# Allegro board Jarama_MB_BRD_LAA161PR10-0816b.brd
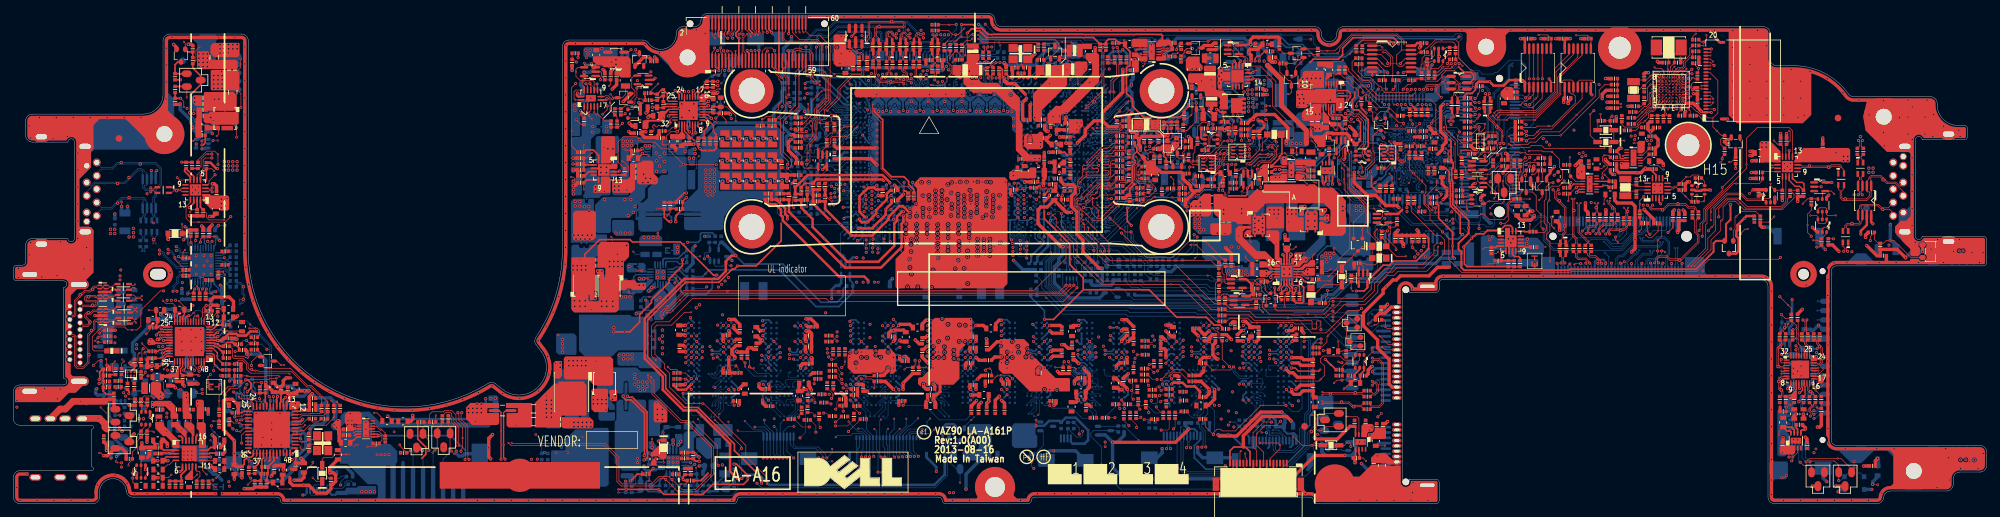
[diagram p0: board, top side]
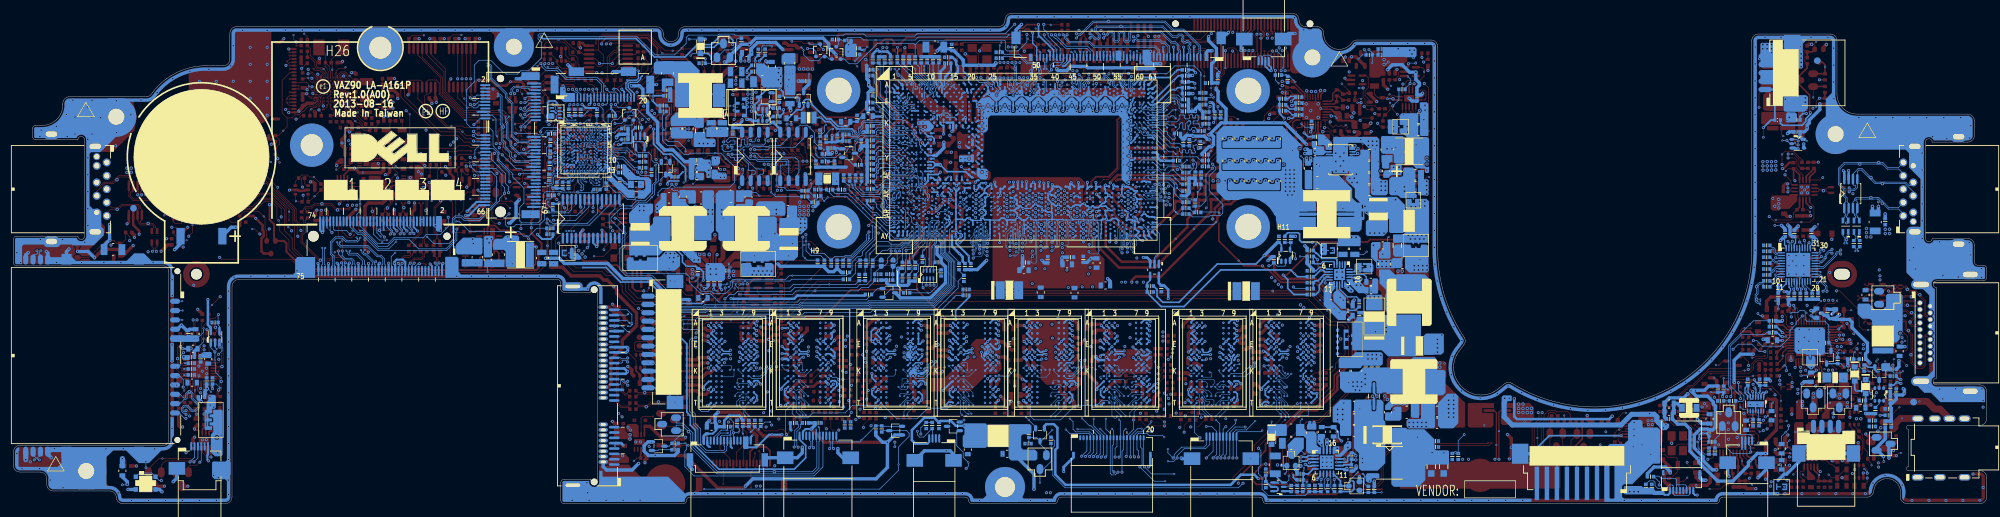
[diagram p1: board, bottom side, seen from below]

Outline 295.3 x 73.5 mm; copper layers: TOP, GND1, IN1, VCC, IN2, IN3, GND2, IN4, GND3, BOTTOM. Coordinates in mm from the lower left corner of the outline.
Outline path: 0,35.25 arc(0.15,35.6) 0.5,35.75 1.34,35.75 arc(1.69,35.9) 1.84,36.25 1.84,38.75 arc(2.13,39.46) 2.84,39.75 8.15,39.75 arc(8.65,39.25) 9.15,39.75 9.15,54.2 arc(8.65,54.7) 8.15,54.2 2.84,54.2 arc(2.13,54.49) 1.84,55.2 1.84,57.4 arc(2.13,58.11) 2.84,58.4 19.4,58.4 arc(21.52,59.28) 22.4,61.4 22.4,69.4 arc(22.69,70.11) 23.4,70.4 34.15,70.4 arc(34.86,70.11) 35.15,69.4 35.15,38 arc(47.22,17.47) 71.03,18.02 arc(71.62,18.17) 72.18,17.95 73.13,17.18 arc(76.07,16.31) 78.76,17.77 78.88,17.92 arc(79.77,20.36) 78.97,22.84 78.24,23.81 arc(78.04,24.38) 78.2,24.97 arc(81.14,31.19) 82.15,38 82.15,68.5 arc(82.44,69.21) 83.15,69.5 94.2,69.5 arc(94.66,69.39) 95.02,69.08 arc(97.59,68.21) 99.2,70.4 99.2,70.5 arc(99.49,71.21) 100.2,71.5 101.9,71.5 arc(102.61,71.79) 102.9,72.5 arc(103.19,73.21) 103.9,73.5 145.9,73.5 arc(146.61,73.21) 146.9,72.5 arc(147.19,71.79) 147.9,71.5 194.75,71.5 arc(195.46,71.21) 195.75,70.5 195.75,70.4 arc(196.9,69.25) 198.05,70.4 198.05,70.5 arc(198.34,71.21) 199.05,71.5 261.9,71.5 arc(262.61,71.21) 262.9,70.5 262.9,66.65 arc(263.19,65.94) 263.9,65.65 266.45,65.65 arc(271.05,64.53) 274.62,61.42 arc(274.97,61.11) 275.43,61 286.9,61 arc(287.61,60.71) 287.9,60 287.9,59.8 arc(288.81,57.61) 291,56.7 291.95,56.7 arc(292.3,56.55) 292.45,56.2 292.45,55.05 arc(292.3,54.7) 291.95,54.55 285.65,54.55 arc(285.15,55.05) 284.65,54.55 284.65,40.1 arc(285.15,39.6) 285.65,40.1 294.8,40.1 arc(295.15,39.95) 295.3,39.6 295.3,36.14 arc(295.15,35.79) 294.8,35.64 272.85,35.64 arc(272.28,35.41) 272.05,34.84 272.05,9.54 arc(272.28,8.97) 272.85,8.74 294.3,8.74 arc(295.01,8.45) 295.3,7.74 295.3,5.74 arc(295.01,5.03) 294.3,4.74 291.3,4.74 arc(290.59,4.45) 290.3,3.74 290.3,2.9 arc(290.01,2.19) 289.3,1.9 280.9,1.9 arc(280.21,1.62) 279.9,0.95 arc(279.59,0.28) 278.9,0 263.58,0 arc(262.87,0.29) 262.58,1 262.58,32.59 arc(262.29,33.3) 261.58,33.59 213.88,33.59 arc(213.53,33.44) 213.38,33.09 213.38,32.17 arc(213.23,31.81) 212.88,31.66 208.88,31.66 208.88,32.06 arc(208.38,32.57) 207.88,32.06 207.88,3.27 arc(208.38,2.77) 208.88,3.27 208.88,3.67 212.88,3.67 arc(213.23,3.52) 213.38,3.17 213.38,0.5 arc(213.23,0.15) 212.88,0 195.05,0 arc(194.7,0.14) 194.55,0.49 arc(194.4,0.84) 194.05,0.98 152.85,0.98 arc(152.5,0.84) 152.35,0.49 arc(152.2,0.14) 151.85,0 139.49,0 arc(139.14,0.14) 138.99,0.49 arc(138.84,0.84) 138.49,0.98 108.81,0.98 arc(108.46,0.84) 108.31,0.49 arc(108.16,0.14) 107.81,0 40.47,0 arc(40.12,0.14) 39.97,0.49 arc(39.82,0.84) 39.47,0.98 17.89,0.98 arc(17.21,1.25) 16.89,1.9 arc(14.82,3.75) 12.9,1.75 12.9,1 arc(12.61,0.29) 11.9,0 1,0 arc(0.29,0.29) 0,1 0,3.95 arc(0.29,4.66) 1,4.95 11.7,4.95 arc(12,5.25) 11.7,5.55 11.7,11.15 arc(12,11.45) 11.7,11.75 1,11.75 arc(0.29,12.04) 0,12.75 0,16.8 arc(0.29,17.51) 1,17.8 7.5,17.8 arc(8,18.3) 7.5,18.8 7.5,32.4 arc(8,32.9) 7.5,33.4 0.5,33.4 arc(0.15,33.55) 0,33.9 0,35.25

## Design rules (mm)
constraint set DEFAULT: min track width 0.109
net group BUS_24MHZ: nets XTAL24_IN XTAL24_OUT
net group BUS_CLK: nets CLK_PCIE_CD CLK_PCIE_CD#
net group BUS_DDRA_CLK: nets M_CLK_A_DDR0 M_CLK_A_DDR#0
net group BUS_DDRB_CLK: nets M_CLK_B_DDR0 M_CLK_B_DDR#0
net group BUS_EDP: nets EDP_TXN_P1 EDP_TXP_P1
net group BUS_HDMI: nets HDMI_CLK HDMI_DAT
net group BUS_PCIE-MINI: nets CLK_PCIE3 CLK_PCIE3#
net group BUS_SPI-CLK-15: nets PCH_SPI_CLK SPI_CLK_ROM
net group DIFFPAIR0: nets CLK_PCIE2 CLK_PCIE2#
net group DIFFPAIR1: nets CLK_PCIE0 CLK_PCIE0#
net group DP_EC-SMB: nets EC_SMB_CK1 EC_SMB_DA1
net group DP_PCIE-PRX-DTX1: nets PCIE_PRX_DTX_N1 PCIE_PRX_DTX_P1
net group DP_PCIE-PRX-DTX4: nets PCIE_PRX_DTX_N4 PCIE_PRX_DTX_P4
net group EDP_TXN_P1_C: nets EDP_TXN_P1_C EDP_TXN_P1_CONN
net group EDP_TXP_P1_C: nets EDP_TXP_P1_C EDP_TXP_P1_CONN
net group HDA_RST_AUDIO#_R: nets HDA_RST_AUDIO#_R HDA_RST_DSP#
net group HDA_SDIN0_DSP: nets HDA_SDIN0_DSP HDA_SDIN0_R
net group HDA_SDOUT_AUDIO_R: nets HDA_SDOUT_AUDIO_R HDA_SDOUT_DSP
net group HDA_SYNC_AUDIO_R: nets HDA_SYNC_AUDIO_R HDA_SYNC_DSP
net group HDMI_CK_N: nets HDMI_CK_N HDMI_CK_N_R
net group HDMI_CK_P: nets HDMI_CK_P HDMI_CK_P_R
net group HDMI_D0_N: nets HDMI_D0_N HDMI_D0_N_R
net group HDMI_D0_P: nets HDMI_D0_P HDMI_D0_P_R
net group HDMI_D1_N: nets HDMI_D1_N HDMI_D1_N_R
net group HDMI_D1_P: nets HDMI_D1_P HDMI_D1_P_R
net group HDMI_D2_N: nets HDMI_D2_N HDMI_D2_N_R
net group HDMI_D2_P: nets HDMI_D2_P HDMI_D2_P_R
net group PA11: nets PA11 USB20_N5
net group PA12: nets PA12 USB20_P5
net group PCH_DDI2_N0: nets PCH_DDI2_N0 PCH_DDI2_N0_C
net group PCH_DDI2_N1: nets PCH_DDI2_N1 PCH_DDI2_N1_C
net group PCH_DDI2_N2: nets PCH_DDI2_N2 PCH_DDI2_N2_C
net group PCH_DDI2_N3: nets PCH_DDI2_N3 PCH_DDI2_N3_C
net group PCH_DDI2_P0: nets PCH_DDI2_P0 PCH_DDI2_P0_C
net group PCH_DDI2_P1: nets PCH_DDI2_P1 PCH_DDI2_P1_C
net group PCH_DDI2_P2: nets PCH_DDI2_P2 PCH_DDI2_P2_C
net group PCH_DDI2_P3: nets PCH_DDI2_P3 PCH_DDI2_P3_C
net group PCH_DP_AUXN: nets PCH_DP_AUXN PCH_DP_AUXN_C
net group PCH_DP_AUXP: nets PCH_DP_AUXP PCH_DP_AUXP_C
net group PCH_DP_N0: nets PCH_DP_N0 PCH_DP_N0_C
net group PCH_DP_N1: nets PCH_DP_N1 PCH_DP_N1_C
net group PCH_DP_N2: nets PCH_DP_N2 PCH_DP_N2_C
net group PCH_DP_N3: nets PCH_DP_N3 PCH_DP_N3_C
net group PCH_DP_P0: nets PCH_DP_P0 PCH_DP_P0_C
net group PCH_DP_P1: nets PCH_DP_P1 PCH_DP_P1_C
net group PCH_DP_P2: nets PCH_DP_P2 PCH_DP_P2_C
net group PCH_DP_P3: nets PCH_DP_P3 PCH_DP_P3_C
net group PCIE_PRX_CARDTX_N2: nets PCIE_PRX_C_CARDTX_N2 PCIE_PRX_CARDTX_N2
net group PCIE_PRX_CARDTX_P2: nets PCIE_PRX_C_CARDTX_P2 PCIE_PRX_CARDTX_P2
net group PCIE_PTX_CARDRX_N2: nets PCIE_PTX_C_CARDRX_N2 PCIE_PTX_CARDRX_N2
net group PCIE_PTX_CARDRX_P2: nets PCIE_PTX_C_CARDRX_P2 PCIE_PTX_CARDRX_P2
net group PCIE_PTX_DRX_N1: nets PCIE_PTX_DRX_N1 PCIE_PTX_DRX_N1_C
net group PCIE_PTX_DRX_N4: nets PCIE_PTX_DRX_N4 PCIE_PTX_DRX_N4_C
net group PCIE_PTX_DRX_P1: nets PCIE_PTX_DRX_P1 PCIE_PTX_DRX_P1_C
net group PCIE_PTX_DRX_P4: nets PCIE_PTX_DRX_P4 PCIE_PTX_DRX_P4_C
net group SATA_PRX_DTX_N0: nets SATA_PRX_DTX_N0 SATA_PRX_DTX_N0_C
net group SATA_PRX_DTX_P0: nets SATA_PRX_DTX_P0 SATA_PRX_DTX_P0_C
net group SATA_PTX_DRX_N0: nets SATA_PTX_DRX_N0 SATA_PTX_DRX_N0_C
net group SATA_PTX_DRX_P0: nets SATA_PTX_DRX_P0 SATA_PTX_DRX_P0_C
net group SD_CLK: nets SD_CLK SD_CLK_R
net group SD_CMD: nets SD_CMD SD_CMD_R
net group SD_D2: nets SD_D2 SD_D2_R
net group SD_D3: nets SD_D3 SD_D3_R
net group SD_LN0_M: nets SD_LN0_M SD_LN0_M_R
net group SD_LN0_P: nets SD_LN0_P SD_LN0_P_R
net group SD_LN1_M: nets SD_LN1_M SD_LN1_M_R
net group SD_LN1_P: nets SD_LN1_P SD_LN1_P_R
net group SD_RCLK_M: nets SD_RCLK_M SD_RCLK_M_R
net group SD_RCLK_P: nets SD_RCLK_P SD_RCLK_P_R
net group SW_USB20_N0: nets SW_USB20_N0 USB20_N0_CONN
net group SW_USB20_N1: nets SW_USB20_N1 USB20_N1_CONN
net group SW_USB20_P0: nets SW_USB20_P0 USB20_P0_CONN
net group SW_USB20_P1: nets SW_USB20_P1 USB20_P1_CONN
net group USB3RN0: nets USB3RN0 USB3RN0_RC_CON
net group USB3RN1: nets USB3RN1 USB3RN1_RC_CON
net group USB3RP0: nets USB3RP0 USB3RP0_RC_CON
net group USB3RP1: nets USB3RP1 USB3RP1_RC_CON
net group USB20_N2: nets USB20_N2 USB20_N2_R
net group USB20_N4: nets USB20_N4 USB20_N4_CONN
net group USB20_N6: nets USB20_N6 USB20_N6_R
net group USB20_P2: nets USB20_P2 USB20_P2_R
net group USB20_P4: nets USB20_P4 USB20_P4_CONN
net group USB20_P6: nets USB20_P6 USB20_P6_R
net group BUS_ASYNCHRONOUS: nets EC_PECI FAN_TEMP0 H_CATERR# MEM_TEMP0 SKIN_TEMP0 SKIN_TEMP1
net group BUS_DDR-A-CMD: nets DDR_A_BS0 DDR_A_BS1 DDR_A_BS2 DDR_A_CAS# DDR_A_MA0 DDR_A_MA1 DDR_A_MA2 DDR_A_MA3 DDR_A_MA4 DDR_A_MA5 DDR_A_MA6 DDR_A_MA7 DDR_A_MA8 DDR_A_MA9 DDR_A_MA10 DDR_A_MA11 DDR_A_MA12 DDR_A_MA13 DDR_A_MA14 DDR_A_MA15 DDR_A_RAS# DDR_A_WE#
net group BUS_DDR-B-CMD: nets DDR_B_BS0 DDR_B_BS1 DDR_B_BS2 DDR_B_CAS# DDR_B_MA0 DDR_B_MA1 DDR_B_MA2 DDR_B_MA3 DDR_B_MA4 DDR_B_MA5 DDR_B_MA6 DDR_B_MA7 DDR_B_MA8 DDR_B_MA9 DDR_B_MA10 DDR_B_MA11 DDR_B_MA12 DDR_B_MA13 DDR_B_MA14 DDR_B_MA15 DDR_B_RAS# DDR_B_WE#
net group BUS_DDRA_CTL: nets DDR_A_CKE0 DDR_A_CKE1 DDR_A_CS0# DDR_A_CS1# M_ODT0
net group BUS_DDRA_D0: nets DDR_A_D0 DDR_A_D1 DDR_A_D2 DDR_A_D3 DDR_A_D4 DDR_A_D5 DDR_A_D6 DDR_A_D7
net group BUS_DDRA_D1: nets DDR_A_D8 DDR_A_D9 DDR_A_D10 DDR_A_D11 DDR_A_D12 DDR_A_D13 DDR_A_D14 DDR_A_D15
net group BUS_DDRA_D2: nets DDR_A_D16 DDR_A_D17 DDR_A_D18 DDR_A_D19 DDR_A_D20 DDR_A_D21 DDR_A_D22 DDR_A_D23
net group BUS_DDRA_D3: nets DDR_A_D24 DDR_A_D25 DDR_A_D26 DDR_A_D27 DDR_A_D28 DDR_A_D29 DDR_A_D30 DDR_A_D31
net group BUS_DDRA_D4: nets DDR_A_D32 DDR_A_D33 DDR_A_D34 DDR_A_D35 DDR_A_D36 DDR_A_D37 DDR_A_D38 DDR_A_D39
net group BUS_DDRA_D5: nets DDR_A_D40 DDR_A_D41 DDR_A_D42 DDR_A_D43 DDR_A_D44 DDR_A_D45 DDR_A_D46 DDR_A_D47
net group BUS_DDRA_D6: nets DDR_A_D48 DDR_A_D49 DDR_A_D50 DDR_A_D51 DDR_A_D52 DDR_A_D53 DDR_A_D54 DDR_A_D55
net group BUS_DDRA_D7: nets DDR_A_D56 DDR_A_D57 DDR_A_D58 DDR_A_D59 DDR_A_D60 DDR_A_D61 DDR_A_D62 DDR_A_D63
net group BUS_DDRA_DQS: nets DDR_A_DQS0 DDR_A_DQS1 DDR_A_DQS2 DDR_A_DQS3 DDR_A_DQS4 DDR_A_DQS5 DDR_A_DQS6 DDR_A_DQS7 DDR_A_DQS#0 DDR_A_DQS#1 DDR_A_DQS#2 DDR_A_DQS#3 DDR_A_DQS#4 DDR_A_DQS#5 DDR_A_DQS#6 DDR_A_DQS#7
net group BUS_DDRB_CTL: nets DDR_B_CKE0 DDR_B_CKE1 DDR_B_CS0# DDR_B_CS1# M_ODT2
net group BUS_DDRB_D0: nets DDR_B_D0 DDR_B_D1 DDR_B_D2 DDR_B_D3 DDR_B_D4 DDR_B_D5 DDR_B_D6 DDR_B_D7
net group BUS_DDRB_D1: nets DDR_B_D8 DDR_B_D9 DDR_B_D10 DDR_B_D11 DDR_B_D12 DDR_B_D13 DDR_B_D14 DDR_B_D15
net group BUS_DDRB_D2: nets DDR_B_D16 DDR_B_D17 DDR_B_D18 DDR_B_D19 DDR_B_D20 DDR_B_D21 DDR_B_D22 DDR_B_D23
net group BUS_DDRB_D3: nets DDR_B_D24 DDR_B_D25 DDR_B_D26 DDR_B_D27 DDR_B_D28 DDR_B_D29 DDR_B_D30 DDR_B_D31
net group BUS_DDRB_D4: nets DDR_B_D32 DDR_B_D33 DDR_B_D34 DDR_B_D35 DDR_B_D36 DDR_B_D37 DDR_B_D38 DDR_B_D39
net group BUS_DDRB_D5: nets DDR_B_D40 DDR_B_D41 DDR_B_D42 DDR_B_D43 DDR_B_D44 DDR_B_D45 DDR_B_D46 DDR_B_D47
net group BUS_DDRB_D6: nets DDR_B_D48 DDR_B_D49 DDR_B_D50 DDR_B_D51 DDR_B_D52 DDR_B_D53 DDR_B_D54 DDR_B_D55
net group BUS_DDRB_D7: nets DDR_B_D56 DDR_B_D57 DDR_B_D58 DDR_B_D59 DDR_B_D60 DDR_B_D61 DDR_B_D62 DDR_B_D63
net group BUS_DDRB_DQS: nets DDR_B_DQS0 DDR_B_DQS1 DDR_B_DQS2 DDR_B_DQS3 DDR_B_DQS4 DDR_B_DQS5 DDR_B_DQS6 DDR_B_DQS7 DDR_B_DQS#0 DDR_B_DQS#1 DDR_B_DQS#2 DDR_B_DQS#3 DDR_B_DQS#4 DDR_B_DQS#5 DDR_B_DQS#6 DDR_B_DQS#7
net group BUS_I2C: nets I2C0_SCK_DSP I2C0_SCK_SNR TP_CLK TP_DATA
net group BUS_I2S: nets BT_PCMCLK BT_PCMFR1 BT_PCMIN BT_PCMOUT I2S_SDI_IN I2S_SDO_OUT I2S_SFRM_OUT
net group BUS_IHDA-CLK: nets HDA_BIT_CLK HDA_BITCLK_AUDIO HDA_BITCLK_DSP
net group BUS_IHDA-DATA: nets HDA_RST# HDA_RST_AUDIO# HDA_SDIN0 HDA_SDIN0_AUDIO HDA_SDOUT HDA_SDOUT_AUDIO HDA_SPKR HDA_SYNC HDA_SYNC_AUDIO
net group BUS_LPC: nets LPC_AD0 LPC_AD1 LPC_AD2 LPC_AD3 LPC_FRAME#
net group BUS_PCIE: nets PCIE_PRX_WLANTX_N3 PCIE_PRX_WLANTX_P3 PCIE_PTX_WLANRX_N3 PCIE_PTX_WLANRX_N3_C PCIE_PTX_WLANRX_P3 PCIE_PTX_WLANRX_P3_C
net group BUS_POWER-RAIL: nets +1.2V_TON BOOT_+1.2V BST_+1.05VS CHG_LGATE CHG_LX CHG_UGATE CPU_B+ DH_+1.2V DL_+1.2V P1 PWM1 SKIP# SKIP#1 SNUB_1.5VSP SNUB_+1.2V SNUB_+1.05V SNUB_CHG SW_+1.2V SW_+1.05VS
net group BUS_SDIO: nets SDIO_CMD SDIO_D0 SDIO_D1 SDIO_D2 SDIO_D3
net group BUS_SPI: nets PCH_SPI_CS# PCH_SPI_IO2 PCH_SPI_IO3 PCH_SPI_SI PCH_SPI_SO SPI_DIN32 SPI_DO32 SPI_IO2_ROM SPI_IO3_ROM SPI_PCH_DO2_32 SPI_PCH_DO3_32 SPI_SI_ROM SPI_SO_ROM TPM_IRQ#
net group BUS_SPK: nets SPK_OUT_L+ SPK_OUT_L- SPK_OUT_R+ SPK_OUT_R-
net group BUS_UART: nets UART1_CTS# UART1_CTS#_NGFF UART1_RTS# UART1_RTS#_NGFF UART1_RXD UART1_RXD_NGFF UART1_TXD UART1_TXD_NGFF
net group BUS_USB2.0: nets I2C1_SCK_TS I2C1_SDA_TS USB20_N0 USB20_N1 USB20_N3 USB20_P0 USB20_P1 USB20_P3
net group CLKOUT_LPC0: nets CLK_LPC_DEBUG CLK_PCI_TPM CLKOUT_LPC0 N48433973
net group CLKOUT_LPC1: nets CLK_PCI_LPC CLKOUT_LPC1 N18675747
net group EDP_AUXN: nets EDP_AUXN EDP_AUXN_C EDP_AUXN_CONN
net group EDP_AUXP: nets EDP_AUXP EDP_AUXP_C EDP_AUXP_CONN
net group EDP_TXN_P0: nets EDP_TXN_P0 EDP_TXN_P0_C EDP_TXN_P0_CONN
net group EDP_TXN_P2: nets EDP_TXN_P2 EDP_TXN_P2_C EDP_TXN_P2_CONN
net group EDP_TXN_P3: nets EDP_TXN_P3 EDP_TXN_P3_C EDP_TXN_P3_CONN
net group EDP_TXP_P0: nets EDP_TXP_P0 EDP_TXP_P0_C EDP_TXP_P0_CONN
net group EDP_TXP_P2: nets EDP_TXP_P2 EDP_TXP_P2_C EDP_TXP_P2_CONN
net group EDP_TXP_P3: nets EDP_TXP_P3 EDP_TXP_P3_C EDP_TXP_P3_CONN
net group I2S_BCLK_OUT: nets I2S_BCLK_OUT I2S_CLK I2S_CLK_IN I2S_SFRM_IN
net group IHDA_DATA-5_10: nets HDA_SDO
net group SPACING-10: nets ALS_SMBDATA DMIC_DAT_CODEC DMIC_DAT_DSP DMIC_DAT_SW I2C0_SDA I2C1_SDA I2C1_SDA_TP PCH_SMBDATA PCH_SMLDATA SENSOR_I2C_SDA SMBDATA SML0DATA SML1DATA
net group SPACING-15: nets 1.05VS_PG_EC 1.05VS_VCCST_PG +V1.05S_AUSB3PLL ALL_SYS_PCH_PWROK_EC ALS_SMBCLK APOWER_OK APWROK_R ARRAY_MIC_CLK BATMAN_CLK BATMAN_DATA CL_CLK DDR3_DRAMRST# DDR_PG_CNTL DELAY_VR_AND_ALL_SYS DMIC_CLK DMIC_CLK_CODEC DMIC_CLK_DSP DMIC_CLK_R DMIC_CLK_SW DSWODVREN EC_SMB_CK1_R H_CPUPWRGD_R H_DRAMRST# H_PROCHOT# H_PROCHOT#_R H_PROCHOT_EC HDA_BITCLK_AUDIO_R HWPG I2C0_SCK I2C1_SCK I2C1_SCK_TP IMVP_VR_PG INV_PWM_R KB_LED_PWM PBTN_OUT# PBTN_OUT#_R PCH_DP_CLK PCH_DPWROK PCH_HDMI_CLK PCH_INTVRMEN PCH_INV_PWM PCH_JTAG_TCK PCH_OPIRCOMP PCH_PLTRST# PCH_PWR_EN PCH_PWROK PCH_PWROK_EC PCH_RSMRST# PCH_RSMRST#_R PCH_RTCRST# PCH_RTCX1 PCH_RTCX2 PCH_SMBCLK PCH_SMLCLK PCH_SRTCRST# PCIE_RCOMP PLT_RST# PM_SLP_A# PM_SLP_S0# PM_SLP_S3# PM_SLP_S4# PM_SLP_S5# PM_SLP_SUS# PM_SYS_RESET# PROC_OPI_COMP RESET# SDIO_CLK SENSOR_I2C_SCL SM_INTRUDER# SM_PG_CTRL SMBCLK SML0CLK SML1CLK SPI_CLK32 SUSCLK SUSCLK_R SYS_PWROK SYS_RESET# SYSTEM_FAN_PWM TD_IREF VCCSTPG_MCP VRPG_MCP VSSSENSE VSSSENSE_R WAKE#
net group SPACING-18: nets H_CPU_SVIDALRT# H_CPU_SVIDCLK H_CPU_SVIDDAT H_PECI H_THERMTRIP# H_THERMTRIP#_R VR_SVID_ALRT# VR_SVID_CLK VR_SVID_DAT
net group USB3TN0: nets USB3TN0 USB3TN0_C USB3TN0_RC_CON
net group USB3TN1: nets USB3TN1 USB3TN1_C USB3TN1_RC_CON
net group USB3TP0: nets USB3TP0 USB3TP0_C USB3TP0_RC_CON
net group USB3TP1: nets USB3TP1 USB3TP1_C USB3TP1_RC_CON
nets with their own width: min track width 0.254; nets +3VS_TS +VCCIO_OUT ECAGND VCCSENSE VCCSENSE_R
nets with their own width: min track width 0.381; nets +3VS_CAM +V1.05S_ASATA3PLL CFG_RCOMP SATA_RCOMP SM_RCOMP0 SM_RCOMP1 SM_RCOMP2
nets with their own width: min track width 0.508; nets 1.2_PGND +0.6VSP +1.2V_B+ +1.2V_FB +1.2VS_DVDD +1.05VA +1.05VS +1.05VS_B+ +1.5VS_D +1.05VS_VCCST +1.05VS_XDP +1.05VSP +1.5VSP +3V_D +3V_PCH +3V_PCH_DSW +3VS_AUDIO +5VS_AUDIO +5VS_KBL +EDP_COM +LCDVDD +LCDVDD_R +PCH_VCCDSW +RTC_VCCSUS +RTCBATT +V1.05A_AOSCSUS +V1.05S_APLLOPI +V1.05S_AXCK_DCB +V1.05S_AXCK_LCPLL +V18R +VCC_CORE +VCCIOA_OUT +VCCP_D +VCHGR +VS_LPSS_SDIO GND VCC
nets with their own width: min track width 1.016; nets +3.3VDX_SSD
nets with their own width: min track width 2.032; nets +5V_USB_P0

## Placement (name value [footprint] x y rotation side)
BRK1  -  [NCQF0_MB_SUP_BRK]  75.8 4.25 0 top
C8  -  [C_0402]  279.38 37.17 0 top
C9  -  [C_0402]  277.59 40.66 0 top
C21  -  [C_0402]  22.13 8.4 180 top
C27  -  [C_0603]  22.32 9.48 180 top
C29  -  [C_0603]  18.4 2.68 0 top
C32  -  [C_0603]  30.68 8.94 270 bottom
C42  -  [C_0603]  18.13 14.37 0 bottom
C43  -  [C_0603]  30.17 9.48 0 top
C44  -  [C_0402]  30.08 8.44 0 top
C45  -  [C_0402]  27.44 3.39 270 top
C46  -  [C_0603]  22.32 6.43 180 top
C47  -  [C_0603]  26.3 2.48 90 top
C48  -  [C_0402]  25.15 3.39 270 top
C50  -  [C_0603]  31.57 6.41 180 top
C51  -  [C_0603]  20.96 5.11 0 top
C96  -  [C_0402]  210.61 69.05 0 top
C265  -  [C_0402]  270.77 52.97 90 top
C276  -  [C_0402]  211.94 53.2 0 top
C277  -  [C_0402]  212.65 50.35 270 top
C278  -  [C_0402]  210.75 52.64 270 top
C279  -  [C_0402]  211.08 53.58 180 top
C280  -  [C_0402]  211.77 49.44 90 top
C281  -  [C_0402]  211.46 54.97 180 top
C282  -  [C_0402]  204.54 47.79 90 bottom
C283  -  [C_0402]  205.42 47.7 270 top
C285  -  [C_0402]  212.21 48.19 270 bottom
C286  -  [C_0402]  205.23 58.15 0 bottom
C293  -  [C_0603]  212.65 55.55 270 top
C303  -  [C_1206]  279.05 38.08 0 bottom
C352  -  [C_0402]  168.08 64.98 180 top
C355  -  [C_0402]  168.63 67.35 0 bottom
C407  -  [C_0402]  196.91 52.36 90 top
C612  -  [C_0402]  90.28 64.45 270 top
C613  -  [C_0402]  90.15 68.16 0 bottom
C617  -  [C_0402]  187.36 48.68 0 top
C621  -  [C_0402]  276.84 53.27 270 top
C623  -  [C_0402]  275.95 53.27 270 top
C655  -  [C_0402]  105.91 39.16 90 bottom
C656  -  [C_0402]  104.13 39.16 90 bottom
C712  -  [C_0603]  223.08 61.43 270 top
C713  -  [C_0402]  250.12 42.45 90 top
C714  -  [C_0402]  249.23 42.45 90 top
C715  -  [C_0402]  224.12 61.7 0 top
C716  -  [C_0603]  225.05 43.23 90 top
C717  -  [C_0603]  230.94 42.34 90 top
C718  -  [C_0402]  224.14 60.82 0 top
C719  -  [C_0603]  204.79 6.46 270 top
C720  -  [C_0402]  204.65 28.57 90 top
C721  -  [C_0402]  204.95 11.08 90 top
C722  -  [C_0402]  203.56 6.47 270 top
C725  -  [C_0603]  226.31 43.23 90 top
C962  -  [C_0603]  261.99 52.56 180 top
C963  -  [C_0402]  261.75 51.42 180 top
C976  -  [C_0402]  244.6 56.41 180 top
C977  -  [C_0402]  252.02 59.6 90 top
C978  -  [C_0402]  245.45 56.37 0 top
C979  -  [C_0402]  252.02 62.34 270 top
C1059  -  [C_0603]  152.47 8.81 270 bottom
C1060  -  [C_0402]  134.69 65.41 90 top
C1061  -  [C_0402]  132.69 65.38 90 top
C1062  -  [C_0402]  135.58 65.41 90 top
C1063  -  [C_0402]  133.58 65.38 90 top
C1064  -  [C_0402]  137.47 64.68 90 top
C1065  -  [C_0402]  138.36 64.68 90 top
C1066  -  [C_0402]  130.68 65.38 90 top
C1067  -  [C_0402]  131.57 65.38 90 top
C1068  -  [C_0402]  129.53 65.44 90 top
C1069  -  [C_0402]  128.64 65.44 90 top
C1102  -  [C_0402]  50.11 2.9 270 bottom
C1107  -  [C_0402]  19.88 38.53 90 bottom
C1108  -  [C_0402]  18.99 38.53 90 bottom
C1109  -  [C_1206]  16.68 40.89 90 bottom
C1110  -  [C_0402]  15.18 41.82 90 bottom
C1116  -  [C_0402]  215.04 50.22 90 bottom
C1117  -  [C_0402]  209.7 55.86 180 top
C1118  -  [C_0402]  209.35 53.58 180 top
C1123  -  [C_0402]  39.34 15.4 0 bottom
C1124  -  [C_0402]  41.55 7.43 90 bottom
C1125  -  [C_0402]  104.59 64.07 270 bottom
C1134  -  [C_0402]  188.87 11.54 180 bottom
C1135  -  [C_0402]  211.13 40.19 270 top
C1136  -  [C_0402]  210.24 40.19 270 top
C1137  -  [C_0402]  210.32 43.8 0 top
C1138  -  [C_0402]  207.4 45.7 180 top
C1139  -  [C_0402]  206.81 40.19 270 top
C1140  -  [C_0402]  207.7 40.19 270 top
C1143  -  [C_0603]  124.52 65.96 270 top
C1145  -  [C_0402]  125.66 65.97 270 top
C1152  -  [C_0402]  240.04 61.07 180 top
C1153  -  [C_0603]  145.87 7.48 0 bottom
C1158  -  [C_0402]  193.49 51.47 180 bottom
C1159  -  [C_0603]  193.73 50.34 180 bottom
C1160  -  [C_0402]  143 9 0 bottom
C1161  -  [C_0402]  50.3 11.16 180 top
C1162  -  [C_0603]  57.6 12.34 0 top
C1163  -  [C_0402]  55.64 10.16 270 top
C1164  -  [C_0402]  191.76 66.02 0 bottom
C1172  -  [C_0603]  30.3 44.88 270 top
C1173  -  [C_0402]  30.41 45.88 90 top
C1199  -  [C_0402]  172.95 69.05 0 top
C1200  -  [C_0402]  165.44 69.06 180 top
C1202  -  [C_0402]  238.8 48.32 0 top
C1203  -  [C_0402]  232.92 47.35 180 top
C1204  -  [C_0402]  248.6 66.12 0 top
C1205  -  [C_0402]  247.74 66.12 180 top
C1209  -  [C_0603]  177.73 62.42 180 top
C1212  -  [C_0402]  34.06 12.58 270 bottom
C1213  -  [C_0402]  35.74 17.75 90 bottom
C1214  -  [C_0402]  34.95 12.58 270 bottom
C1215  -  [C_0402]  235.77 51.37 270 top
C1216  -  [C_0402]  196.07 54.85 0 top
C1219  -  [C_0402]  234.63 50.45 90 top
C1225  -  [C_0402]  175.33 12.1 180 bottom
C1227  -  [C_0402]  180.84 57.26 0 top
C1228  -  [C_0402]  186.05 61.32 0 top
C1230  -  [C_0402]  193.71 49.95 0 top
C1231  -  [C_0603]  192.78 52.81 180 top
C1237  -  [C_0402]  117.91 53.32 180 top
C1240  -  [C_0603]  181.79 64.82 90 bottom
C1241  -  [C_0402]  182.81 67.22 90 bottom
C1242  -  [C_0402]  183.83 67.22 90 bottom
C1243  -  [C_0402]  186.04 62.21 0 top
C1244  -  [C_0402]  184.8 65.71 180 bottom
C1245  -  [C_0402]  206.57 48.07 270 bottom
C1246  -  [C_0402]  215.95 45.19 0 top
C1247  -  [C_0402]  193.71 49.06 0 top
C1248  -  [C_0402]  244.79 52.37 0 top
C1251  -  [C_0402]  209.8 52.7 270 top
C1252  -  [C_0402]  207.57 53.04 90 top
C1253  -  [C_0402]  207.51 47.1 0 bottom
C1254  -  [C_0402]  239.91 52.81 180 top
C1256  -  [C_0402]  244.76 55.06 0 top
C1257  -  [C_0402]  244.79 53.25 0 top
C1261  -  [C_0402]  185.62 31.34 0 top
C1262  -  [C_0402]  185.32 32.24 0 top
C1278  -  [C_0402]  168.63 68.24 0 bottom
C1280  -  [C_0402]  49.38 10.27 0 top
C1281  -  [C_0402]  54.74 9.03 180 top
C1282  -  [C_0402]  116.47 50.55 0 bottom
C1283  -  [C_0402]  218.07 53.64 180 top
C1284  -  [C_0402]  220.82 55.1 0 top
C1285  -  [C_0402]  232.34 69.71 180 top
C1286  -  [C_0402]  232.14 60.82 0 top
C1287  -  [C_0402]  226.17 69.71 0 top
C1288  -  [C_0402]  224.84 63.49 270 top
C1289  -  [C_0402]  261.17 47.05 270 top
C1290  -  [C_0402]  27.92 55.74 0 bottom
C1292  -  [C_0402]  238.8 47.43 0 top
C1294  -  [C_0402]  244.94 50.15 0 top
C1295  -  [C_0402]  242.89 47.79 90 top
C1296  -  [C_0402]  242.88 46.85 270 top
C1297  -  [C_0402]  264.72 8.29 90 top
C1298  -  [C_0402]  265.31 13.83 180 top
C1299  -  [C_0402]  202.37 11.59 90 top
C1300  -  [C_0402]  266.81 11.82 0 top
C1301  -  [C_0402]  268.41 8.29 90 top
C1302  -  [C_0402]  204.02 11.08 90 top
C1303  -  [C_0402]  200.72 11.59 90 top
C1304  -  [C_0402]  201.43 6.84 180 top
CA1  -  [C_0603]  43.49 6.07 270 top
CA2  -  [C_0603]  33.65 14.77 180 top
CA3  -  [C_0603]  33.07 5.82 270 top
CA4  -  [C_0402]  42.22 6.09 270 top
CA5  -  [C_0402]  33.66 13.63 180 top
CA6  -  [C_0402]  34.22 5.58 270 top
CA7  -  [C_0603]  42.22 16.56 90 top
CA8  -  [C_0603]  38.93 16.73 90 top
CA9  -  [C_0603]  40.31 5.74 270 top
CA10  -  [C_0402]  40.06 16.6 90 top
CA11  -  [C_0402]  41.08 16.54 90 top
CA12  -  [C_0402]  39.04 5.58 270 top
CA13  -  [C_0402]  38.1 5.5 180 top
CA14  -  [C_0402]  37.9 3.42 270 top
CA15  -  [C_0402]  37.01 3.42 270 top
CA16  -  [C_0402]  44.2 9.62 90 top
CA17  -  [C_0402]  44.2 8.75 270 top
CA18  -  [C_0402]  47.03 12.71 0 bottom
CA19  -  [C_0603]  46.82 15.02 0 bottom
CA20  -  [C_0603]  46.82 13.78 0 bottom
CA21  -  [C_0603]  38.86 3.16 0 top
CA22  -  [C_0603]  41.47 12.01 90 bottom
CA23  -  [C_0603]  34.22 25.83 90 top
CA24  -  [C_0402]  29.75 28.91 180 top
CA25  -  [C_0603]  21.58 27.54 180 top
CA26  -  [C_0402]  33.2 23.91 0 top
CA27  -  [C_0402]  34.05 20.94 180 top
CA28  -  [C_0402]  13.46 17.45 0 top
CA29  -  [C_0402]  14.29 12.38 270 bottom
CA30  -  [C_0402]  16.19 20.25 270 top
CA31  -  [C_0402]  23.81 28.23 90 bottom
CA32  -  [C_0402]  18.15 20.73 90 top
CA33  -  [C_0402]  31.68 24.8 0 top
CA34  -  [C_0402]  21.34 26.4 180 top
CA35  -  [C_0402]  31.35 26.83 0 top
CA36  -  [C_0603]  23.3 19.1 270 top
CA37  -  [C_0402]  24.44 19.24 270 top
CA38  -  [C_0402]  20.06 14.77 90 top
CA39  -  [C_0603]  26.3 18.27 90 bottom
CA40  -  [C_0402]  25.33 18.32 90 top
CA41  -  [C_0402]  31.41 22.72 0 top
CA42  -  [C_0603]  32.89 27.92 180 top
CA43  -  [C_0603]  32.76 24.49 180 bottom
CA44  -  [C_0603]  25.58 29.07 180 top
CA45  -  [C_0603]  26.47 17.95 90 top
CA46  -  [C_0603]  22.66 27.73 90 bottom
CA47  -  [C_0402]  32.26 20.05 180 top
CA48  -  [C_0402]  32.26 19.16 180 top
CA49  -  [C_0402]  30.59 29.68 270 top
CA50  -  [C_0402]  31.62 27.41 0 bottom
CA51  -  [C_0603]  25.47 27.86 90 bottom
CA52  -  [C_A1]  23.9 18.91 180 bottom
CA53  -  [C_0402]  21.44 14.08 0 top
CA54  -  [C_0402]  26.9 14.09 180 top
CA55  -  [C_0402]  24.86 14.12 180 top
CA56  -  [C_0402]  29.15 14.17 180 top
CA57  -  [C_0603]  19.23 6.9 90 top
CA58  -  [C_0402]  30.79 11.46 90 top
CA67  -  [C_0603]  21.46 20.62 180 top
CA68  -  [C_0402]  16.14 17.51 180 top
CA69  -  [C_0402]  17.56 11.57 180 bottom
CA70  -  [C_0402]  15.3 20.25 270 top
CA71  -  [C_0402]  14.41 17.78 270 bottom
CA74  -  [C_0402]  19.89 21.67 0 bottom
CC160  -  [C_0603]  132.57 32.71 180 bottom
CC161  -  [C_0603]  133.2 35.37 90 bottom
CC162  -  [C_0603]  141.55 32.38 270 bottom
CC163  -  [C_0603]  136.88 35.88 0 bottom
CC164  -  [C_0603]  143.36 34.99 0 bottom
CC165  -  [C_0603]  136.5 32.32 270 bottom
CC233  -  [C_0402]  140.52 37.02 270 bottom
CC234  -  [C_0402]  135.18 37.08 270 bottom
CC238  -  [C_0402]  136.63 36.94 0 bottom
CC239  -  [C_0402]  143.36 36.13 0 bottom
CC240  -  [C_0402]  123.51 32.7 270 bottom
CD1  -  [C_0402]  99.76 17.82 180 top
CD2  -  [C_0402]  112.18 17.18 0 top
CD3  -  [C_0402]  108.71 24.63 270 top
CD4  -  [C_0402]  118.61 20.99 0 top
CD5  -  [C_0402]  107.74 15.41 0 top
CD14  -  [C_0402]  108.71 26.54 270 top
CD15  -  [C_0402]  107.13 25.26 180 top
CD16  -  [C_0402]  107.13 19.6 180 top
CD17  -  [C_0402]  119.45 25.19 180 top
CD18  -  [C_0402]  119.45 23.53 180 top
CD19  -  [C_0402]  120.28 26.53 180 top
CD20  -  [C_0603]  109.46 16.49 90 top
CD21  -  [C_0603]  119.03 18 180 top
CD22  -  [C_B2]  112.19 31.86 0 bottom
CD24  -  [C_0402]  127.17 16.85 90 top
CD25  -  [C_0402]  136.95 17.18 0 top
CD26  -  [C_0402]  133.01 21.38 0 top
CD27  -  [C_0402]  146.37 21.5 180 top
CD28  -  [C_0402]  133.43 15.41 180 top
CD37  -  [C_0402]  143.58 21.12 180 top
CD38  -  [C_0402]  136.01 23.1 270 top
CD39  -  [C_0402]  137.73 16.3 180 top
CD40  -  [C_0402]  144.08 23.41 180 top
CD41  -  [C_0402]  143.17 25.06 0 top
CD42  -  [C_0402]  144.08 17.82 180 top
CD43  -  [C_0603]  137.98 14.64 180 top
CD44  -  [C_0603]  144.55 16.3 0 top
CD45  -  [C_0402]  159.43 18.84 0 top
CD46  -  [C_0402]  148.12 17.95 0 top
CD47  -  [C_0402]  156.9 23.02 270 top
CD48  -  [C_0402]  165.78 21.12 0 top
CD49  -  [C_0402]  155.11 15.41 0 top
CD58  -  [C_0402]  158.43 24.21 270 top
CD59  -  [C_0402]  158.61 22.47 270 top
CD60  -  [C_0402]  156.9 25.56 90 top
CD61  -  [C_0402]  167.63 26.55 270 top
CD62  -  [C_0402]  166.61 26.15 270 top
CD63  -  [C_0402]  166.11 17.87 90 top
CD64  -  [C_0603]  164.84 18.77 270 top
CD65  -  [C_0603]  160.45 16.68 180 top
CD66  -  [C_B2]  147.61 31.99 0 bottom
CD68  -  [C_0402]  174.36 19.04 270 top
CD69  -  [C_0402]  178.44 15.98 180 top
CD70  -  [C_0402]  179.89 25.33 270 top
CD71  -  [C_0402]  194.51 20.73 90 top
CD72  -  [C_0402]  178.44 12.68 180 top
CD81  -  [C_0402]  178.24 25.33 270 top
CD82  -  [C_0402]  177.43 26.27 180 top
CD83  -  [C_0402]  183.19 24.42 90 top
CD84  -  [C_0402]  191.88 26.27 0 top
CD85  -  [C_0402]  192.02 25.4 270 top
CD86  -  [C_0402]  194.49 16.92 90 top
CD87  -  [C_0603]  178.43 14.71 180 top
CD88  -  [C_0603]  194.75 15.92 270 top
CD89  -  [C_0402]  121.47 45.32 90 top
CD90  -  [C_0402]  119.69 46.24 0 top
CD91  -  [C_0402]  116.06 45.58 90 top
CD92  -  [C_0402]  117.89 45.53 0 top
CD93  -  [C_0402]  160.52 13.93 90 top
CD94  -  [C_0402]  174.75 13.83 0 top
CD95  -  [C_0402]  174.59 16.78 0 top
CD96  -  [C_0402]  148.33 13.55 90 top
CD97  -  [C_0402]  171.69 22.32 90 top
CD98  -  [C_0402]  167.63 23.88 90 top
CD101  -  [C_0603]  117.57 15.47 90 top
CD102  -  [C_0402]  120.84 19.6 180 top
CD103  -  [C_0402]  145.66 13.55 90 top
CD104  -  [C_0402]  113.66 14.62 180 top
CD105  -  [C_0402]  161.16 12.87 0 top
CD106  -  [C_0402]  146.93 13.55 90 top
CD107  -  [C_0402]  143.37 13.55 90 top
CD110  -  [C_0603]  158.36 13.82 90 top
CD111  -  [C_0402]  154.24 19.6 180 top
CD112  -  [C_0402]  111.18 24.06 270 top
CD113  -  [C_0603]  111.18 25.07 90 top
CD114  -  [C_0603]  99.62 25.32 90 top
CD115  -  [C_0402]  99.69 23.74 270 top
CD116  -  [C_0402]  145.67 23.08 90 top
CD117  -  [C_0603]  158.43 25.12 90 top
CD118  -  [C_0603]  147 26.27 180 top
CD119  -  [C_0402]  130.98 25.07 0 top
CD120  -  [C_0402]  136.01 24.88 270 top
CD121  -  [C_0603]  133.55 25.7 270 top
CD122  -  [C_0603]  136.01 26.4 180 top
CD123  -  [C_0402]  186.37 26.48 270 top
CD124  -  [C_0402]  171.7 24.99 270 top
CD125  -  [C_0603]  185.22 26.46 270 top
CD126  -  [C_0603]  173.54 25.07 90 top
CH1  -  [C_0402]  115.98 63.05 0 bottom
CH2  -  [C_0402]  171.81 47.07 180 bottom
CH3  -  [C_0402]  174.46 47.07 0 bottom
CH4  -  [C_0402]  165.47 34.4 0 bottom
CH5  -  [C_0402]  163.7 34.4 0 bottom
CH6  -  [C_0402]  187.65 56.32 270 bottom
CH7  -  [C_0402]  181.49 57.16 180 bottom
CH11  -  [C_0402]  145.1 67.67 270 top
CH16  -  [C_0402]  145.99 67.67 270 top
CH23  -  [C_0402]  150.34 65.37 180 top
CH24  -  [C_0402]  151.18 65.37 0 top
CH25  -  [C_0402]  264.34 24.54 90 top
CH26  -  [C_0402]  265.23 24.54 90 top
CH39  -  [C_0402]  158.17 54.03 270 top
CH40  -  [C_0402]  158.25 55.99 180 top
CH41  -  [C_0402]  158.25 57.01 180 top
CH47  -  [C_0402]  156.6 52.69 180 top
CH82  -  [C_0402]  156.72 48.75 180 top
CH83  -  [C_0402]  157.28 47.81 270 top
CH84  -  [C_0402]  158.17 47.81 270 top
CH85  -  [C_0402]  154.3 46.33 270 top
CH95  -  [C_0402]  260.53 43.11 270 top
CH1202  -  [C_0402]  244.05 63.51 90 top
CH1203  -  [C_0402]  244.05 62.65 270 top
CH1204  -  [C_0603]  151.33 49.22 90 top
CH1205  -  [C_0402]  150.25 49.52 90 top
CH1206  -  [C_0402]  165.08 51.47 0 top
CH1207  -  [C_0402]  155.96 47.86 180 top
CH1208  -  [C_0805]  179.09 59.97 90 bottom
CH1209  -  [C_0805]  179.75 58.02 180 top
CH1210  -  [C_0805]  179.14 66.87 270 bottom
CH1211  -  [C_0805]  179.97 66.78 180 top
CH1212  -  [C_A1]  143.65 65.01 180 top
CH1213  -  [C_0402]  151.39 51.67 180 top
CH1214  -  [C_0402]  169.04 57.31 90 bottom
CH1215  -  [C_0402]  154.27 51.04 90 top
CH1216  -  [C_0402]  155.23 57.34 270 top
CH1217  -  [C_0603]  156.27 57.45 270 top
CH1218  -  [C_0402]  150.16 47.06 180 top
CH1220  -  [C_0603]  157.22 51.16 180 top
CH1222  -  [C_0402]  158.17 48.8 90 top
CH1223  -  [C_0603]  157.22 49.89 180 top
CH1224  -  [C_0402]  171.89 47.25 270 top
CH1225  -  [C_0603]  156.79 53.83 180 top
CH1226  -  [C_0402]  154.34 56.68 180 top
CH1227  -  [C_0402]  185.86 68.11 90 top
CH1228  -  [C_A1]  156.09 65.01 180 top
CH1229  -  [C_0402]  153.42 57.56 0 top
CH1230  -  [C_1206]  156.07 68.44 0 bottom
CH1231  -  [C_0402]  154.87 67.93 90 bottom
CH1232  -  [C_0402]  158.17 50.71 90 top
CH1233  -  [C_0402]  152.38 48.24 0 top
CH1234  -  [C_0402]  153.65 54.85 0 top
CH1235  -  [C_0402]  152.13 53.5 90 top
CH1236  -  [C_0402]  85.24 61.27 270 bottom
CH1237  -  [C_0402]  146.61 65.34 270 top
CH1238  -  [C_0402]  145.73 65.34 270 top
CH1239  -  [C_0603]  170.06 57.26 0 bottom
CH1240  -  [C_A1]  168.37 56.82 0 top
CH1241  -  [C_0402]  120.36 65.03 180 bottom
CH1242  -  [C_0402]  252.16 42.83 90 top
CH1243  -  [C_0402]  251.28 42.83 90 top
CLRP1  -  [SHORTPADS]  165.42 36.05 270 bottom
CLRP2  -  [SHORTPADS]  163.65 36.05 90 bottom
CR1  -  [C_0603]  267.85 18.14 0 bottom
CR2  -  [C_0402]  266.5 16.06 270 top
CR3  -  [C_0402]  269.12 25.05 90 bottom
CR4  -  [C_0603]  268.04 24.75 90 bottom
CR5  -  [C_0402]  278.64 5.65 180 top
CR6  -  [C_0603]  269.12 23.22 180 bottom
CR7  -  [C_0603]  266.5 14.14 270 top
CR8  -  [C_0402]  266.38 18.86 270 bottom
CR9  -  [C_0402]  267.9 16.06 270 top
CR10  -  [C_0603]  267.9 14.14 270 top
CR11  -  [C_0402]  267.28 22.16 270 bottom
CR12  -  [C_0603]  266.13 22.4 270 bottom
CR13  -  [C_0402]  265.23 15.15 90 top
CR14  -  [C_0402]  264.34 15.15 90 top
CR19  -  [C_0603]  278.99 5.63 270 bottom
CR20  -  [C_0402]  270.55 14.3 270 top
CS42  -  [C_0402]  202.13 14.17 0 top
CS43  -  [C_0402]  202.13 15.08 0 top
CS53  -  [C_0402]  202.14 16.05 0 top
CS54  -  [C_0402]  202.14 16.94 0 top
CV8  -  [C_0402]  237.42 42.45 90 top
CV10  -  [C_0402]  236.53 42.45 90 top
CV27  -  [C_0402]  33.35 35.17 180 bottom
CV28  -  [C_0402]  33.35 36.95 180 bottom
CV29  -  [C_0402]  33.35 38.73 180 bottom
CV30  -  [C_0402]  33.35 34.28 180 bottom
CV31  -  [C_0402]  25.22 31.56 270 bottom
CV32  -  [C_0402]  29.66 31.56 270 bottom
CV33  -  [C_0402]  33.35 36.06 180 bottom
CV34  -  [C_0402]  33.35 37.84 180 bottom
CV35  -  [C_0402]  33.35 32.5 180 bottom
CV36  -  [C_0402]  33.35 33.39 180 bottom
CV37  -  [C_0402]  241.86 42.86 270 top
CV38  -  [C_0402]  233.46 38.72 270 top
CV39  -  [C_0402]  31.18 31.56 270 bottom
CV40  -  [C_0603]  18.13 32 270 bottom
CV41  -  [C_0603]  13.02 22.14 90 bottom
CV42  -  [C_0402]  30.17 40.04 90 bottom
CV43  -  [C_0402]  26.23 40.04 90 bottom
CV44  -  [C_0402]  28.77 40.04 90 bottom
CV45  -  [C_0402]  240.09 43.37 270 top
CV46  -  [C_0402]  236.12 38.72 270 top
CV47  -  [C_0402]  234.35 38.72 270 top
CV48  -  [C_0402]  239.2 43.37 270 top
CV49  -  [C_0402]  240.98 42.86 270 top
CV50  -  [C_0402]  235.24 38.72 270 top
CV768  -  [C_0402]  14.59 24.21 180 top
CV795  -  [C_0402]  14.59 25.1 180 top
CV796  -  [C_0402]  14.59 25.99 180 top
D3  -  [RB751V-40GTE-17_SOD323-2]  19.74 20.49 270 bottom
D4  -  [RB751V-40GTE-17_SOD323-2]  18.1 18.6 270 bottom
D72  -  [BAT54CW_SOT323-3]  174.55 68.88 180 bottom
D81  -  [SDMK0340L-7-F_SOD323-2]  46.22 3.35 90 top
D83  -  [BAT54CW_SOT323-3]  204.67 55.93 180 top
D86  -  [SDMK0340L-7-F_SOD323-2]  239.51 54.21 180 top
D87  -  [SDMK0340L-7-F_SOD323-2]  239.51 55.99 180 top
D93  -  [DB2J31400L_SOD323-2]  189.75 55.35 180 top
D104  -  [BAT54CW_SOT323-3]  203.14 59.35 180 bottom
D105  -  [BAT54CW_SOT323-3]  93.82 58.45 270 top
D106  -  [BAT54CW_SOT323-3]  172.15 68.5 180 bottom
D110  -  [BAT1000-7-F_SOT23-3]  14.01 30.87 90 bottom
D111  -  [RB751V-40GTE-17_SOD323-2]  25.25 40.5 180 top
D114  -  [SDMK0340L-7-F_SOD323-2]  195.99 8.75 0 top
D115  -  [BAT54CW_SOT323-3]  233.04 49.07 270 top
D301  -  [DB2J31400L_SOD323-2]  194.19 32.33 270 top
D302  -  [DB2J31400L_SOD323-2]  203.35 38.59 0 top
D303  -  [DB2J31400L_SOD323-2]  205.45 36.81 180 top
D305  -  [SDMK0340L-7-F_SOD323-2]  198.81 35.22 270 top
D306  -  [BAT54CW_SOT323-3]  201.22 37.9 180 top
D307  -  [BAT54CW_SOT323-3]  188.14 31.55 0 top
DA1  -  [PJDLC05_SOT23-3]  17.35 13.19 90 top
DA2  -  [PJDLC05_SOT23-3]  14.4 8.96 90 bottom
DA3  -  [PJDLC05C_SOT23-3]  22.04 14.44 180 bottom
DA4  -  [PJDLC05C_SOT23-3]  25.98 14.44 180 bottom
DA5  -  [PJDLC05_SOT23-3]  17.35 9.25 90 top
DA6  -  [PJDLC05_SOT23-3]  38.6 13.7 0 bottom
DA8  -  [PJDLC05_SOT23-3]  274.12 2.62 0 top
DA9  -  [PJDLC05_SOT23-3]  270.06 2.62 0 top
DE1  -  [PESD5V0U2BT_SOT23-3]  196.28 12.56 270 top
DE2  -  [PESD5V0U2BT_SOT23-3]  198.21 11.92 270 bottom
DH5  -  [RB751V-40_SOD323-2]  192.47 67.49 90 bottom
DV4  -  [AZ1045-04F_DFN2510P10E-10-9]  13.83 27.18 90 top
DV5  -  [AZ1045-04F_DFN2510P10E-10-9]  12.95 32.73 270 top
F1  -  [F_1812L075-24DR]  150.1 10.17 180 bottom
FD1  -  [FIDUCIAL_C40M80]  25.34 66.4 180 bottom
FD2  -  [FIDUCIAL_C40M80]  10.93 15.22 180 bottom
FD3  -  [FIDUCIAL_C40M80]  277.32 44.28 180 bottom
FD4  -  [FIDUCIAL_C40M80]  15.8 54.75 0 top
FD5  -  [FIDUCIAL_C40M80]  273.06 57.81 0 top
FD6  -  [FIDUCIAL_C40M80]  193.22 11.59 0 top
FV2  -  [F_SMD1812P110TF]  15.53 27.3 270 bottom
H1  -  [H_2P4]  100.9 66.9 0 top
H2  -  [H_2P4]  279.9 58 0 top
H4  -  [H_3P0]  146.9 2.5 0 top
H6  -  [H_2P4]  22.6 55.4 0 top
H7  -  [H_2P4]  220.4 68.5 0 top
H9  -  [H_3P9]  171.8 41.5 0 top
H10  -  [H_3P9]  110.5 61.9 0 top
H11  -  [H_3P9]  110.5 41.5 0 top
H12  -  [H_3P9]  171.8 61.9 0 top
H15  -  [H_3P3]  250.65 53.74 0 top
H18  -  [H_2P4]  284.4 4.9 0 top
H19  -  [H_1P6N]  267.9 34.4 0 top
H20  -  [H_2P4X1P6N]  21.65 34.4 0 top
H26  -  [H_3P3]  240.39 68.34 0 top
JAPS  -  [E-T_6705K-Y18N-00L_18P]  190.57 6.07 0 top
JBATT1  -  [FOX_GS73091-10272-7H_9P-T]  55.31 3.04 180 bottom
JBL1  -  [ACES_51522-00401-001_4P-T]  156.75 9.79 180 bottom
JCARD  -  [T-SOL_156-2001302603_19P-T]  271.1 30.34 270 bottom
JDCIN1  -  [ACES_50281-00501-001_5P-T]  33.15 62.08 90 bottom
JDEBUG  -  [ACES_50281-0120N-001_12P]  200.33 31.12 90 bottom
JFAN1  -  [HB_A510810-SCHR21_8P]  47.4 1.99 0 bottom
JHDMI  -  [ACON_HMR2G-AK120C_19P-T]  9.98 30.1 90 bottom
JHP1  -  [SINGA_2SJ3061-030111F_6P-T]  10.3 3.95 90 bottom
JKB1  -  [ACES_51522-01001-001_10P]  116.76 10.05 180 bottom
JKB2  -  [ACES_50696-02001-001_20P-T]  135.65 9.88 180 bottom
JLVDS1  -  [ACES_50406-02071-001_20P]  211.9 60.86 180 bottom
JLVDS2  -  [STARC_300E50-0011RA-G3_50P]  117.65 66.9 0 bottom
JNFC1  -  [HB_A531515-SCHR21_15P-T]  191.95 9.44 180 bottom
JNGFF1  -  [LOTES_APCI0019-P001A01_67P-T]  217.12 62.99 270 bottom
JNGFF2  -  [JAE_SM3ZS067U215ALL_75P-T]  231.15 34.86 0 bottom
JP1  -  [JUMP_43X118]  265.2 12.56 0 bottom
JPA1  -  [JUMP_43X39]  29.57 17.51 0 top
JPA2  -  [JUMP_43X39]  30.22 2.52 0 bottom
JPA3  -  [JUMP_43X39]  26.41 21.5 90 bottom
JPWR1  -  [HB_A520620-SCHR22_6P]  268.68 8.58 180 bottom
JROT1  -  [ACES_51522-00401-001_4P-T]  108.93 66.34 0 bottom
JSATA1  -  [LCN_DAN08-52216-0100_52P]  205.38 5.86 270 bottom
JSNRDG  -  [ACES_50696-02001-001_20P-T]  253.29 58.66 90 top
JSPK1  -  [CVILU_CI4304M2HR0-NH_4P]  25.9 11.58 180 bottom
JTP1  -  [ACES_51522-01201-001_12P]  177.65 10.18 180 bottom
JUSB1  -  [TAIWI_USB022-107CRL-TW_10P-T]  282.82 50.65 270 bottom
JUSB2  -  [TAIWI_USB022-107CRL-TW_10P-T]  10.98 43.65 90 bottom
JVOL  -  [ACES_51522-00401-001_4P-T]  35.1 9.45 180 bottom
JXDP  -  [SAMTE_BSH-030-01-L-D-A_60P]  104.07 66.41 0 top
L1  -  [MURAT_BLM21PG600SN1D_2P]  19.64 17.32 0 top
L2  -  [MURAT_BLM18PG181SN1D_L0603_2P]  24.14 11.88 90 top
L3  -  [MURAT_BLM18PG181SN1D_L0603_2P]  21.77 11.85 90 top
L4  -  [MURAT_BLM18PG181SN1D_L0603_2P]  26.17 11.83 90 top
L5  -  [MURAT_BLM18PG181SN1D_L0603_2P]  28 11.83 90 top
L43  -  [KC_FBMA-L11-160808-800LMT_2P]  201.35 46.36 0 bottom
L44  -  [KC_FBMA-L11-160808-800LMT_2P]  201.38 47.86 0 bottom
L61  -  [MURAT_LQM2MPN2R2NG0L_2P]  159.31 65.13 180 top
L62  -  [MURAT_LQM2MPN2R2NG0L_2P]  159.61 67.93 180 top
L63  -  [MURAT_LQM2MPN2R2NG0L_2P]  175.49 57.87 0 bottom
L64  -  [MURAT_DLW21SN900HQ2L_0805_4P]  15.6 30.42 0 top
L65  -  [MURAT_DLW21SN900HQ2L_0805_4P]  15.6 32.07 0 top
L66  -  [MURAT_DLW21SN900HQ2L_0805_4P]  15.73 28.64 0 top
L67  -  [MURAT_DLW21SN900HQ2L_0805_4P]  15.73 26.99 0 top
LA1  -  [CYNTE_PG031B-4R7MS_2P]  45.62 14.36 180 bottom
LED2  -  [LED_LTW-C193TS5_2P]  15.48 22.9 180 top
LH2  -  [MURAT_BLM18BA220SN1D_2P]  22.56 29 180 top
LH10  -  [MURAT_LQM2MPN2R2NG0L_2P]  179.32 61.49 270 top
LH11  -  [MURAT_LQM2MPN2R2NG0L_2P]  179.08 63.65 90 top
LH12  -  [MURAT_LQM2MPN2R2NG0L_2P]  143.58 68.6 270 top
MC94  -  [C_0402]  182.89 55.51 90 top
MC95  -  [C_0402]  174.57 55.09 90 bottom
MC96  -  [C_0402]  159.25 37.08 270 bottom
MC102  -  [C_0402]  166 50.6 180 top
MC103  -  [C_0402]  156.47 35.05 270 bottom
MC104  -  [C_0402]  183.01 47.23 180 top
MC105  -  [C_0402]  210.56 55.86 0 top
MC118  -  [C_0402]  166 52.43 180 top
MC284  -  [C_0402]  214.94 53.68 90 bottom
MC654  -  [C_0402]  210.38 58.2 90 bottom
MC1133  -  [C_0402]  209.73 63.48 180 top
MC1141  -  [C_0402]  209.61 45.91 270 top
MC1151  -  [C_0402]  170.86 69.43 180 bottom
MC1210  -  [C_0402]  210.67 67.67 0 top
MC1211  -  [C_0402]  206.43 63.48 0 top
MC1212  -  [C_0402]  205.31 63.48 180 top
MC1267  -  [C_0402]  144.44 13.53 90 top
MC1268  -  [C_0402]  174.67 15.46 0 top
MC1269  -  [C_0402]  116.95 49.26 0 top
MC1270  -  [C_0402]  122.88 53.63 90 top
MC1271  -  [C_0402]  122.87 51.72 90 top
MC1272  -  [C_0402]  114.99 51.29 270 top
MC1273  -  [C_0402]  92.91 20.05 90 bottom
MC1274  -  [C_0402]  91.13 20.05 90 bottom
MC1275  -  [C_0402]  92.02 20.05 90 bottom
MC1276  -  [C_0402]  32.14 35.8 180 top
MC1277  -  [C_0402]  32.14 37.83 180 top
MD50  -  [IP4223CZ6_SO6]  215.16 64.05 270 top
MD74  -  [AZ1065-06QPRDG_MSOP8]  278.02 47.62 180 top
MD82  -  [AZ1065-06QPRDG_MSOP8]  21.3 44.29 180 bottom
MD90  -  [IP4223CZ6_SO6]  125.09 68.91 0 top
ML40  -  [MURAT_DLW21HN900SQ2L_4P]  273.1 49.47 270 top
ML45  -  [MURAT_DLW21SN670HQ2L_4P]  276.01 51.12 270 top
ML46  -  [MURAT_DLW21SN670HQ2L_4P]  274.59 39.16 90 top
ML49  -  [SW_WCM2012F2S_4P]  220.19 58.94 90 top
ML50  -  [SW_WCM2012F2S_4P]  232.31 39.12 270 top
ML52  -  [MURAT_DLW21HN900SQ2L_4P]  23.26 47.44 180 top
ML53  -  [MURAT_DLW21SN670HQ2L_4P]  19.06 40.75 90 bottom
ML54  -  [MURAT_DLW21SN670HQ2L_4P]  20.71 40.75 90 bottom
ML55  -  [MURAT_DLW21HN900SQ2L_4P]  216.13 58.85 90 top
ML56  -  [MURAT_DLW21SN670HQ2L_4P]  133.55 67.65 90 top
ML57  -  [MURAT_DLW21SN670HQ2L_4P]  135.58 67.65 90 top
ML58  -  [MURAT_DLW21SN670HQ2L_4P]  138.32 67.65 90 top
ML59  -  [MURAT_DLW21SN670HQ2L_4P]  131.52 67.65 90 top
ML60  -  [MURAT_DLW21SN670HQ2L_4P]  129.49 67.65 90 top
MR226  -  [R_0402]  214.97 52.87 270 bottom
MR256  -  [R_0402]  183.75 56.12 0 top
MR257  -  [R_0402]  174.57 54.22 270 bottom
MR976  -  [R_0402]  208.72 44.99 90 top
NOREF  -  []  279.9 58 0 top
NOREF#2  -  []  220.4 68.5 0 top
NOREF#3  -  []  38.88 -157.64 0 top
NOREF#4  -  []  106.06 4.54 0 top
NOREF#5  -  []  100.9 66.9 0 top
NOREF#6  -  []  134.37 10.83 0 top
NOREF#7  -  []  284.4 4.9 0 top
NOREF#8  -  []  110.5 61.9 0 top
NOREF#9  -  []  171.8 41.5 0 top
NOREF#10  -  []  171.79 61.89 0 top
NOREF#11  -  []  250.65 53.74 0 top
NOREF#12  -  []  154.81 2.9 0 top
NOREF#13  -  []  7 120.23 0 top
NOREF#14  -  []  240.39 68.34 0 top
NOREF#15  -  []  110.49 61.89 0 top
NOREF#16  -  []  110.49 41.48 0 top
NOREF#17  -  []  267.9 34.4 0 top
NOREF#18  -  []  220.4 68.5 0 top
NOREF#19  -  []  161.9 -39.16 0 top
NOREF#20  -  []  171.79 41.48 0 top
NOREF#21  -  []  21.65 34.4 0 top
NOREF#22  -  []  22.62 55.4 0 top
NOREF#23  -  []  22.6 55.4 0 top
NOREF#24  -  []  110.5 41.5 0 top
NOREF#25  -  []  146.9 2.5 0 top
NOREF#26  -  []  171.8 61.9 0 top
NOREF#27  -  []  100.9 66.9 0 top
NOREF#28  -  []  197.73 2.98 0 top
NOREF#29  -  []  78.4 8.64 0 top
NOREF#30  -  []  108.51 34.15 0 top
NOREF#31  -  []  197.75 2.9 0 top
NOREF#32  -  []  117.41 1.73 0 top
NOREF#33  -  []  14.9 1.75 0 top
NOREF#34  -  []  250.84 62.66 180 bottom
NOREF#35  -  []  85.49 1.25 180 bottom
NOREF#36  -  []  245.67 50.34 180 bottom
NOREF#37  -  []  216.58 26.45 180 bottom
PBJ1  -  [BJ_CR2016-L01-JHLF_2P]  264.02 40.1 0 bottom
PC101  -  [C_0402]  33.2 64.55 90 top
PC102  -  [C_0402]  32.31 64.55 90 top
PC103  -  [C_0402]  28.85 59.93 180 top
PC104  -  [C_0402]  28.85 60.82 180 top
PC105  -  [C_0402]  82.95 9.38 180 bottom
PC106  -  [C_0402]  82.95 8.49 180 bottom
PC107  -  [C_0402]  79.97 6.61 90 bottom
PC108  -  [C_0402]  79.08 6.61 90 bottom
PC112  -  [C_0402]  100.53 1.81 90 bottom
PC113  -  [C_0402]  104.08 2.73 270 bottom
PC114  -  [C_0603]  196.86 22.84 0 top
PC115  -  [C_0603]  201.54 18.09 180 top
PC116  -  [C_0402]  195.41 22.53 180 top
PC202  -  [C_0402]  81.4 11.79 0 top
PC203  -  [C_0402]  81.4 12.68 0 top
PC204  -  [C_0805]  81.39 13.83 0 bottom
PC205  -  [C_0805]  81.39 12.05 0 bottom
PC208  -  [C_0402]  28.85 59.04 180 top
PC209  -  [C_0402]  28.85 58.15 180 top
PC210  -  [C_0402]  99.99 6.78 0 top
PC211  -  [C_0402]  101.75 6.75 90 top
PC212  -  [C_0402]  100.91 7.64 180 top
PC213  -  [C_0603]  95.81 7.41 270 top
PC214  -  [C_0805]  101 9.8 90 bottom
PC216  -  [C_0402]  100.51 4.35 90 top
PC217  -  [C_0805]  94.29 19.06 90 bottom
PC218  -  [C_0603]  99.5 11.48 270 bottom
PC219  -  [C_0805]  96.07 19.06 90 bottom
PC220  -  [C_0402]  98.66 4.43 0 top
PC221  -  [C_0603]  89.57 12.99 90 bottom
PC223  -  [C_0805]  93.82 14.58 0 bottom
PC224  -  [C_0805]  93.82 12.67 0 bottom
PC225  -  [C_0805]  93.82 10.89 0 bottom
PC227  -  [C_0402]  95.07 7.6 270 bottom
PC228  -  [C_0402]  95.07 5.82 270 bottom
PC229  -  [C_0402]  92.53 2.6 270 bottom
PC318  -  [C_0603]  194.43 34.78 0 top
PC324  -  [C_0805]  198.02 45.83 180 bottom
PC326  -  [C_B2]  201.49 40.14 270 bottom
PC328  -  [C_0805]  180.24 43.92 180 bottom
PC329  -  [C_0603]  185.29 46.66 270 bottom
PC333  -  [C_0603]  195.13 46.72 270 bottom
PC334  -  [C_B2]  179.25 39.38 270 bottom
PC335  -  [C_0603]  185.41 34.59 0 top
PC342  -  [C_0603]  190.56 38.15 90 top
PC343  -  [C_0402]  181.92 42.65 270 top
PC345  -  [C_0402]  181.03 42.65 270 top
PC347  -  [C_0603]  191.4 30.84 0 bottom
PC426  -  [C_0805]  85.88 55.99 180 bottom
PC427  -  [C_0603]  89.86 50.59 270 bottom
PC428  -  [C_0805]  86.34 49.31 180 bottom
PC429  -  [C_0402]  84.45 50.91 0 top
PC430  -  [C_0805]  85.88 57.77 180 bottom
PC432  -  [C_0805]  86.34 47.53 180 bottom
PC433  -  [C_0402]  85.36 48.12 180 top
PC434  -  [C_0805]  214.45 37.66 270 bottom
PC436  -  [C_0805]  225.86 37.78 270 bottom
PC437  -  [C_0402]  227.03 38.45 0 top
PC439  -  [C_0603]  224.33 35.86 90 bottom
PC440  -  [C_0402]  223.7 35.53 90 top
PC441  -  [C_0805]  216.22 37.66 270 bottom
PC501  -  [C_0402]  197.06 61.16 0 bottom
PC502  -  [C_0402]  199.33 56.93 90 top
PC503  -  [C_0603]  195.61 65.93 270 top
PC504  -  [C_0603]  196.4 56.31 90 top
PC505  -  [C_0805]  190.87 57.09 270 bottom
PC506  -  [C_0805]  187.98 63.04 180 bottom
PC507  -  [C_0805]  187.98 64.77 180 bottom
PC508  -  [C_0805]  189.17 57.09 270 bottom
PC509  -  [C_0402]  197.96 62.05 180 bottom
PC510  -  [C_0805]  194.37 57.08 270 bottom
PC511  -  [C_0402]  194.32 57.74 270 top
PC512  -  [C_0402]  195.21 57.74 270 top
PC513  -  [C_0805]  196.14 57.08 270 bottom
PC602  -  [C_0805]  86.58 36.05 0 bottom
PC603  -  [C_0402]  86.72 36.56 0 top
PC604  -  [C_0402]  86.72 35.67 0 top
PC605  -  [C_0603]  92.83 31.99 180 bottom
PC606  -  [C_0805]  96.32 37.36 90 bottom
PC607  -  [C_0805]  94.54 37.36 90 bottom
PC608  -  [C_0603]  94.88 29.7 0 bottom
PC609  -  [C_0402]  100.77 37.96 0 bottom
PC610  -  [C_B]  91.65 26.36 90 bottom
PC611  -  [C_B2]  86.26 23.66 0 bottom
PC612  -  [C_0603]  96.27 28.18 180 bottom
PC613  -  [C_0603]  89.66 38.72 0 bottom
PC614  -  [C_0402]  101.68 36.18 180 bottom
PC615  -  [C_0402]  93.91 27.72 90 bottom
PC616  -  [C_0402]  100.77 33.13 0 bottom
PC701  -  [C_0805]  93.24 48.75 180 bottom
PC702  -  [C_0805]  93.24 46.97 180 bottom
PC703  -  [C_0805]  93.25 52.31 180 bottom
PC704  -  [C_0805]  93.25 50.53 180 bottom
PC705  -  [C_B2]  91.03 44.44 90 bottom
PC707  -  [C_0603]  105.85 59.48 90 top
PC708  -  [C_0402]  104.7 62.39 90 top
PC709  -  [C_0402]  103.38 60.05 180 bottom
PC710  -  [C_0402]  92.7 49.77 0 top
PC711  -  [C_0402]  93.41 52.95 180 top
PC712  -  [C_0603]  101.54 50.97 270 bottom
PC713  -  [C_0603]  99.83 52.69 0 bottom
PC714  -  [C_0402]  96.34 61.39 270 top
PC715  -  [C_0603]  98.75 55.04 270 top
PC717  -  [C_0603]  96.32 59.42 180 top
PC718  -  [C_0402]  103.82 62.39 90 top
PC720  -  [C_0603]  94.49 56.61 180 top
PC721  -  [C_0402]  93.86 55.53 180 top
PC724  -  [C_0402]  94.54 60.49 0 top
PC725  -  [C_0402]  92.7 48.88 0 top
PC726  -  [C_0402]  92.7 50.66 0 top
PC801  -  [C_0805]  106.48 49.22 270 top
PC802  -  [C_0805]  106.48 49.22 270 bottom
PC803  -  [C_0805]  113.59 52.27 270 top
PC804  -  [C_0805]  111.82 52.27 270 top
PC805  -  [C_0805]  111.82 52.27 270 bottom
PC806  -  [C_0805]  108.26 55.57 270 bottom
PC807  -  [C_0805]  110.04 52.27 270 top
PC808  -  [C_0805]  108.26 52.27 270 bottom
PC809  -  [C_0805]  115.37 49.22 270 top
PC810  -  [C_0805]  113.59 49.22 270 top
PC811  -  [C_0805]  111.82 49.22 270 top
PC812  -  [C_0805]  113.61 55.57 270 bottom
PC813  -  [C_0805]  111.83 55.57 270 bottom
PC814  -  [C_0805]  110.04 49.22 270 top
PC815  -  [C_0805]  111.82 55.57 270 top
PC816  -  [C_0805]  110.04 55.57 270 top
PC817  -  [C_0805]  113.59 55.57 270 top
PC818  -  [C_0805]  113.59 52.27 270 bottom
PC819  -  [C_0805]  110.04 52.27 270 bottom
PC820  -  [C_0805]  110.05 55.57 270 bottom
PC821  -  [C_0805]  108.26 49.22 270 top
PC822  -  [C_0805]  106.48 52.27 270 top
PC823  -  [C_0805]  108.26 52.27 270 top
PC824  -  [C_0805]  106.48 55.57 270 top
PC825  -  [C_0805]  108.26 55.57 270 top
PC826  -  [C_0805]  106.48 55.57 270 bottom
PC827  -  [C_0805]  106.48 52.27 270 bottom
PC828  -  [C_0805]  108.26 49.22 270 bottom
PC829  -  [C_0805]  110.04 49.22 270 bottom
PC830  -  [C_0805]  111.82 49.22 270 bottom
PD103  -  [PESD24VS2UT_SOT23-3]  64.4 8.45 0 top
PD104  -  [PESD24VS2UT_SOT23-3]  60.33 8.39 0 top
PD201  -  [RB751V-40_SOD323-2]  107 11.03 270 bottom
PD202  -  [BAT54HT1G_SOD323-2]  97.3 9.47 270 top
PD204  -  [SX34H_SMA2]  91.56 10.32 180 bottom
PH701  -  [R_0402]  105.81 59.8 180 bottom
PH702  -  [R_0402]  98.29 45.14 270 top
PJP304  -  [JUMP_43X118]  201.49 37.36 270 bottom
PJP306  -  [JUMP_43X118]  183.83 36.47 270 bottom
PJP409  -  [JUMP_43X39]  85.79 45.02 90 bottom
PJP410  -  [JUMP_43X39]  87.24 56.5 0 bottom
PJP411  -  [JUMP_43X39]  227.65 35.92 90 top
PJP412  -  [JUMP_43X39]  212.86 37.57 180 bottom
PJP501  -  [JUMP_43X118]  186.99 59.42 180 bottom
PJP601  -  [JUMP_43X79]  85.41 39.27 270 bottom
PJP602  -  [JUMP_43X118]  94.76 24.62 0 bottom
PJP603  -  [JUMP_43X39]  97.9 37.96 0 bottom
PJP604  -  [JUMP_43X39]  92.7 35.54 0 bottom
PL101  -  [TAI-T_HCB2012KF-121T50_2P]  32.84 62.7 270 top
PL102  -  [MURAT_BLM15AG102SN1D_2P]  31.7 57.5 180 bottom
PL104  -  [TAI-T_HCB2012KF-121T50_2P]  30.04 67.91 270 top
PL105  -  [TAI-T_HCB2012KF-121T50_2P]  83.11 6.53 270 bottom
PL106  -  [TAI-T_HCB2012KF-121T50_2P]  81.25 6.53 270 bottom
PL201  -  [TAI-T_HCB2012KF-121T50_2P]  76.84 12.3 0 top
PL202  -  [TAI-T_HCB2012KF-121T50_2P]  76.84 14.21 0 top
PL203  -  [CYNTE_PCMB063T-2R2MS_2P]  82.68 18.3 0 bottom
PL302  -  [TOKO_FDSD0630-H-3R3M-P3_2P]  188.53 41.26 180 bottom
PL303  -  [TOKO_FDSD0630-H-2R2M-P3_2P]  198.03 41.26 180 bottom
PL304  -  [KC_FBMA-L11-201209-121LMA50_2P]  178.63 45.58 0 top
PL405  -  [TAIYO_NRS4018T1R0NDGJ_2P]  87.83 52.81 180 bottom
PL406  -  [TAIYO_NRS4018T1R0NDGJ_2P]  220.8 37.32 180 bottom
PL501  -  [TAI-T_HCB2012KF-121T50_2P]  192.59 54.86 90 bottom
PL502  -  [CYNTE_PCMC063T-R68MN_2P]  195.24 61.2 180 bottom
PL601  -  [TAI-T_HCB2012KF-121T50_2P]  88.19 39.72 270 bottom
PL602  -  [CYNTE_PCMB063T-2R2MS_2P]  86.42 27.16 90 bottom
PL701  -  [MAG_MMD06CZER15MG_4P]  94.49 43.39 0 bottom
PL703  -  [KC_FBMA-L11-453215800LMA90T_2P]  84.53 42.4 0 bottom
PQ101  -  [FDV301N-G_SOT23-3]  28.03 63.48 90 top
PQ102  -  [MMST3904-7-F_SOT323-3]  25.08 66.22 0 top
PQ103  -  [2N7002KDWH_SOT363-6]  105.19 1.87 90 bottom
PQ104  -  [2N7002KW_SOT323-3]  199.99 24.29 270 top
PQ105  -  [DMN66D0LDW-7_SOT363-6]  202.12 22.29 180 top
PQ106  -  [2N7002KW_SOT323-3]  199.51 27.08 270 top
PQ201  -  [CSD87312Q3E_SON8-4]  31.68 59.24 180 top
PQ202  -  [2N7002KW_SOT323-3]  104.08 7.29 0 bottom
PQ203  -  [SIR472DP-T1-GE3_POWERPAK8-5]  85.43 19.42 180 top
PQ204  -  [2N7002KW_SOT323-3]  95.46 2.65 270 bottom
PQ205  -  [SI7716ADN-T1-GE3_POWERPAK8-5]  87.46 16.58 0 top
PQ206  -  [AO4407AL_SO8]  91.93 8.03 270 bottom
PQ304  -  [CSD87330Q3D_SON8-7]  195.73 41.75 90 top
PQ305  -  [CSD87330Q3D_SON8-7]  184.89 42.4 270 top
